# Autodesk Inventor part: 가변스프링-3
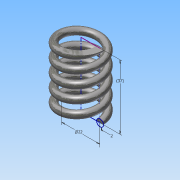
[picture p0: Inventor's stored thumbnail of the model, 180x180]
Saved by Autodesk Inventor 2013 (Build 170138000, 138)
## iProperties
Created: 2016-01
Part Number: 가변스프링-3
Material: 스테인리스강
Document SubType Name: Modeling
Designer: Administrator
Mass: 34.2793 g
Surface Area: 43.3134 cm^2
Volume: 4.24249 cm^3
Density: 8.08 g/cm^3
Author: Administrator
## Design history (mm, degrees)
sketch "스케치1"
  geometry: L1 (0, 0)-(11, 0); L2 (11, 0)-(11, 36.411); L3 (11, 36.411)-(0, 36.411); L4 (0, 36.411)-(0, 0); C1 r 2 at (11, 0)
  constraints: 8 end point, 2 parallel, 1 centre point, 1 coincident, 1 horizontal, 1 perpendicular
  dimensions: "d0" = 2 radius of C1; "d1" = 22 diameter of L2 L4; "d2" = 36.4112 distance between parallel lines of L3 L1 (derived)
feature "코일1" sketch "스케치1" pitch "d3" = 10; turns "d5" = 5; dims "d4" = 36.4112 (= d2), "d6" = 0, angle "d7" = 90 deg, angle "d8" = 90 deg, "d9" = 0, "d10" = 0
feature "분할1"
node "작업 평면1"
feature "분할2"
node "솔리드1"
other parameters: "d11" = 90 deg
